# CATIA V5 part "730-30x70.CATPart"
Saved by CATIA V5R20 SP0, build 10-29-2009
Part number: 730-30x70
Definition: NONE
Nomenclature: 730-30x70
Source: Unknown
Description: 730-30x70
Bounding box of the stored display mesh (mm): x -19 to 19, y -18.312 to 18.312, z 0 to 70
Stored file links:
  C:\Users\Utente\Desktop\IO LAVORO\3D X SITO CF\X SITO\730\730-30x70.CATPart
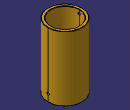
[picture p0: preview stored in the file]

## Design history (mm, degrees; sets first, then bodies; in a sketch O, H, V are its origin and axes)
Body1 "730-30x70" (main body)
  Solid1: solid without history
